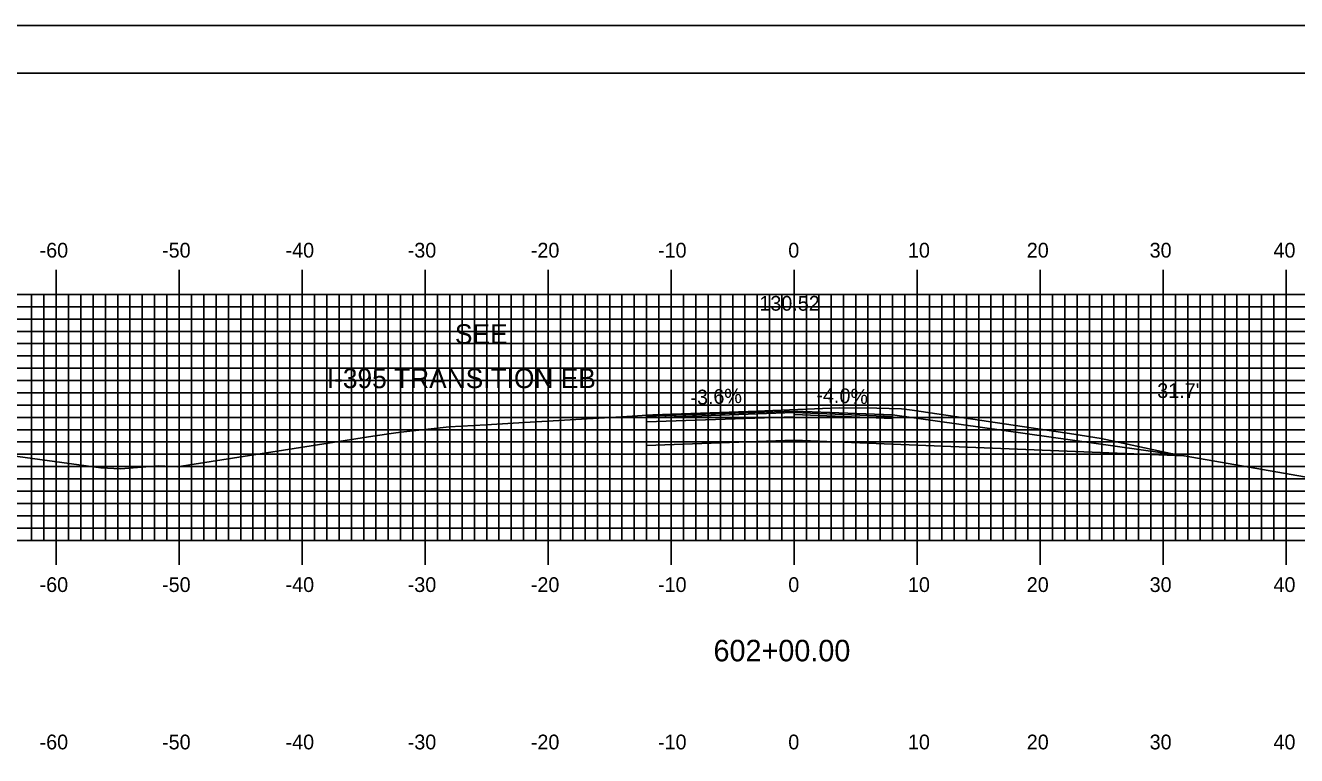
# Model space of a CAD drawing. Extents: x 841388 to 841731, y 363538 to 363758.
# Drawn here: x 841491.4 to 841594.7, y 363698.2 to 363757.6 of the extents above; entities that cross this region are included whole.
import ezdxf

# ---------------------------------------------------------------- set-up
doc = ezdxf.new("R2010")
doc.units = 0
for name, color, linetype in [('ANNOTATION', 7, 'Continuous'), ('BORDER', 7, 'Continuous'), ('D_Roadway_Centerline', 7, 'Continuous'), ('D_Roadway_Centerline_Text', 7, 'Continuous'), ('D_Roadway_Edge_Shoulder', 7, 'Continuous'), ('D_Roadway_Edge_TW', 7, 'Continuous'), ('D_Roadway_SubGrade', 7, 'Continuous'), ('D_Text_Standard', 7, 'Continuous'), ('H_V ANNOTATION', 7, 'Continuous'), ('M_Roadway_Centerline', 7, 'Continuous'), ('MAJOR', 7, 'Continuous'), ('MINOR', 7, 'Continuous'), ('PLOT BOUNDARY', 7, 'Continuous'), ('S_Roadway_Centerline', 7, 'Continuous')]:
    doc.layers.add(name, color=color, linetype=linetype)

msp = doc.modelspace()

# ---------------------------------------------------------------- linework, layer by layer
at = {"layer": 'ANNOTATION'}
for p, q in [((841541.86, 363725.68), (841541.86, 363723.43)), ((841553.86, 363726.12), (841553.86, 363723.87)), ((841561.86, 363725.8), (841561.86, 363723.55))]:
    msp.add_line(p, q, dxfattribs=at)
at = {"layer": 'BORDER'}
msp.add_lwpolyline([(841404.26, 363543.72), (841724.26, 363543.72), (841724.26, 363753.72), (841404.26, 363753.72)], close=True, dxfattribs=at)
at = {"layer": 'D_Roadway_Centerline'}
msp.add_lwpolyline([(841541.86, 363725.81), (841553.86, 363726.24), (841561.86, 363725.92)], dxfattribs=at)
at = {"layer": 'D_Roadway_Edge_Shoulder'}
msp.add_lwpolyline([(841553.86, 363726.24), (841561.86, 363725.92), (841561.86, 363725.8), (841553.86, 363726.12)], close=True, dxfattribs=at)
at = {"layer": 'D_Roadway_Edge_TW'}
msp.add_lwpolyline([(841541.86, 363725.81), (841553.86, 363726.24), (841553.86, 363726.12), (841541.86, 363725.68)], close=True, dxfattribs=at)
msp.add_lwpolyline([(841541.86, 363725.81), (841541.86, 363725.68)], dxfattribs=at)
at = {"layer": 'D_Roadway_SubGrade'}
for p, q in [((841541.86, 363734.28), (841541.86, 363725.68)), ((841541.86, 363725.68), (841541.86, 363723.43)), ((841553.86, 363726.12), (841553.86, 363723.87)), ((841561.86, 363725.8), (841561.86, 363723.55))]:
    msp.add_line(p, q, dxfattribs=at)
for points in [[(841553.86, 363726.12), (841553.86, 363725.78), (841541.86, 363725.35)], [(841541.86, 363725.68), (841541.86, 363723.43), (841553.86, 363723.87), (841561.86, 363723.55)], [(841553.86, 363726.12), (841553.86, 363725.95), (841561.86, 363725.63)], [(841561.86, 363723.55), (841585.53, 363722.6), (841561.86, 363725.92)]]:
    msp.add_lwpolyline(points, dxfattribs=at)
at = {"layer": 'MAJOR'}
for p, q in [((841493.86, 363737.73), (841493.86, 363735.72)), ((841503.86, 363737.73), (841503.86, 363735.72)), ((841513.86, 363737.73), (841513.86, 363735.72)), ((841523.86, 363737.73), (841523.86, 363735.72)), ((841533.86, 363737.73), (841533.86, 363735.72)), ((841543.86, 363737.73), (841543.86, 363735.72)), ((841553.86, 363737.73), (841553.86, 363735.72)), ((841563.86, 363737.73), (841563.86, 363735.72)), ((841573.86, 363737.73), (841573.86, 363735.72)), ((841583.86, 363737.73), (841583.86, 363735.72)), ((841593.86, 363737.73), (841593.86, 363735.72)), ((841413.86, 363735.72), (841693.86, 363735.72)), ((841413.86, 363735.72), (841693.86, 363735.72)), ((841493.86, 363715.72), (841493.86, 363735.72)), ((841503.86, 363715.72), (841503.86, 363735.72)), ((841513.86, 363715.72), (841513.86, 363735.72)), ((841523.86, 363715.72), (841523.86, 363735.72)), ((841533.86, 363715.72), (841533.86, 363735.72)), ((841543.86, 363715.72), (841543.86, 363735.72)), ((841553.86, 363715.72), (841553.86, 363735.72)), ((841563.86, 363715.72), (841563.86, 363735.72)), ((841573.86, 363715.72), (841573.86, 363735.72)), ((841583.86, 363715.72), (841583.86, 363735.72)), ((841593.86, 363715.72), (841593.86, 363735.72)), ((841413.86, 363730.72), (841693.86, 363730.72)), ((841413.86, 363725.72), (841693.86, 363725.72)), ((841413.86, 363720.72), (841693.86, 363720.72)), ((841413.86, 363715.72), (841693.86, 363715.72)), ((841413.86, 363715.72), (841693.86, 363715.72)), ((841493.86, 363713.72), (841493.86, 363715.72)), ((841503.86, 363713.72), (841503.86, 363715.72)), ((841513.86, 363713.72), (841513.86, 363715.72)), ((841523.86, 363713.72), (841523.86, 363715.72)), ((841533.86, 363713.72), (841533.86, 363715.72)), ((841543.86, 363713.72), (841543.86, 363715.72)), ((841553.86, 363713.72), (841553.86, 363715.72)), ((841563.86, 363713.72), (841563.86, 363715.72)), ((841573.86, 363713.72), (841573.86, 363715.72)), ((841583.86, 363713.72), (841583.86, 363715.72)), ((841593.86, 363713.72), (841593.86, 363715.72))]:
    msp.add_line(p, q, dxfattribs=at)
at = {"layer": 'MINOR'}
for p, q in [((841491.86, 363715.72), (841491.86, 363735.72)), ((841492.86, 363715.72), (841492.86, 363735.72)), ((841494.86, 363715.72), (841494.86, 363735.72)), ((841495.86, 363715.72), (841495.86, 363735.72)), ((841496.86, 363715.72), (841496.86, 363735.72)), ((841497.86, 363715.72), (841497.86, 363735.72)), ((841498.86, 363715.72), (841498.86, 363735.72)), ((841499.86, 363715.72), (841499.86, 363735.72)), ((841500.86, 363715.72), (841500.86, 363735.72)), ((841501.86, 363715.72), (841501.86, 363735.72)), ((841502.86, 363715.72), (841502.86, 363735.72)), ((841504.86, 363715.72), (841504.86, 363735.72)), ((841505.86, 363715.72), (841505.86, 363735.72)), ((841506.86, 363715.72), (841506.86, 363735.72)), ((841507.86, 363715.72), (841507.86, 363735.72)), ((841508.86, 363715.72), (841508.86, 363735.72)), ((841509.86, 363715.72), (841509.86, 363735.72)), ((841510.86, 363715.72), (841510.86, 363735.72)), ((841511.86, 363715.72), (841511.86, 363735.72)), ((841512.86, 363715.72), (841512.86, 363735.72)), ((841514.86, 363715.72), (841514.86, 363735.72)), ((841515.86, 363715.72), (841515.86, 363735.72)), ((841516.86, 363715.72), (841516.86, 363735.72)), ((841517.86, 363715.72), (841517.86, 363735.72)), ((841518.86, 363715.72), (841518.86, 363735.72)), ((841519.86, 363715.72), (841519.86, 363735.72)), ((841520.86, 363715.72), (841520.86, 363735.72)), ((841521.86, 363715.72), (841521.86, 363735.72)), ((841522.86, 363715.72), (841522.86, 363735.72)), ((841524.86, 363715.72), (841524.86, 363735.72)), ((841525.86, 363715.72), (841525.86, 363735.72)), ((841526.86, 363715.72), (841526.86, 363735.72)), ((841527.86, 363715.72), (841527.86, 363735.72)), ((841528.86, 363715.72), (841528.86, 363735.72)), ((841529.86, 363715.72), (841529.86, 363735.72)), ((841530.86, 363715.72), (841530.86, 363735.72)), ((841531.86, 363715.72), (841531.86, 363735.72)), ((841532.86, 363715.72), (841532.86, 363735.72)), ((841534.86, 363715.72), (841534.86, 363735.72)), ((841535.86, 363715.72), (841535.86, 363735.72)), ((841536.86, 363715.72), (841536.86, 363735.72)), ((841537.86, 363715.72), (841537.86, 363735.72)), ((841538.86, 363715.72), (841538.86, 363735.72)), ((841539.86, 363715.72), (841539.86, 363735.72)), ((841540.86, 363715.72), (841540.86, 363735.72)), ((841541.86, 363715.72), (841541.86, 363735.72)), ((841542.86, 363715.72), (841542.86, 363735.72)), ((841544.86, 363715.72), (841544.86, 363735.72)), ((841545.86, 363715.72), (841545.86, 363735.72)), ((841546.86, 363715.72), (841546.86, 363735.72)), ((841547.86, 363715.72), (841547.86, 363735.72)), ((841548.86, 363715.72), (841548.86, 363735.72)), ((841549.86, 363715.72), (841549.86, 363735.72)), ((841550.86, 363715.72), (841550.86, 363735.72)), ((841551.86, 363715.72), (841551.86, 363735.72)), ((841552.86, 363715.72), (841552.86, 363735.72)), ((841554.86, 363715.72), (841554.86, 363735.72)), ((841555.86, 363715.72), (841555.86, 363735.72)), ((841556.86, 363715.72), (841556.86, 363735.72)), ((841557.86, 363715.72), (841557.86, 363735.72)), ((841558.86, 363715.72), (841558.86, 363735.72)), ((841559.86, 363715.72), (841559.86, 363735.72)), ((841560.86, 363715.72), (841560.86, 363735.72)), ((841561.86, 363715.72), (841561.86, 363735.72)), ((841562.86, 363715.72), (841562.86, 363735.72)), ((841564.86, 363715.72), (841564.86, 363735.72)), ((841565.86, 363715.72), (841565.86, 363735.72)), ((841566.86, 363715.72), (841566.86, 363735.72)), ((841567.86, 363715.72), (841567.86, 363735.72)), ((841568.86, 363715.72), (841568.86, 363735.72)), ((841569.86, 363715.72), (841569.86, 363735.72)), ((841570.86, 363715.72), (841570.86, 363735.72)), ((841571.86, 363715.72), (841571.86, 363735.72)), ((841572.86, 363715.72), (841572.86, 363735.72)), ((841574.86, 363715.72), (841574.86, 363735.72)), ((841575.86, 363715.72), (841575.86, 363735.72)), ((841576.86, 363715.72), (841576.86, 363735.72)), ((841577.86, 363715.72), (841577.86, 363735.72)), ((841578.86, 363715.72), (841578.86, 363735.72)), ((841579.86, 363715.72), (841579.86, 363735.72)), ((841580.86, 363715.72), (841580.86, 363735.72)), ((841581.86, 363715.72), (841581.86, 363735.72)), ((841582.86, 363715.72), (841582.86, 363735.72)), ((841584.86, 363715.72), (841584.86, 363735.72)), ((841585.86, 363715.72), (841585.86, 363735.72)), ((841586.86, 363715.72), (841586.86, 363735.72)), ((841587.86, 363715.72), (841587.86, 363735.72)), ((841588.86, 363715.72), (841588.86, 363735.72)), ((841589.86, 363715.72), (841589.86, 363735.72)), ((841590.86, 363715.72), (841590.86, 363735.72)), ((841591.86, 363715.72), (841591.86, 363735.72)), ((841592.86, 363715.72), (841592.86, 363735.72)), ((841413.86, 363734.72), (841693.86, 363734.72)), ((841413.86, 363733.72), (841693.86, 363733.72)), ((841413.86, 363732.72), (841693.86, 363732.72)), ((841413.86, 363731.72), (841693.86, 363731.72)), ((841413.86, 363729.72), (841693.86, 363729.72)), ((841413.86, 363728.72), (841693.86, 363728.72)), ((841413.86, 363727.72), (841693.86, 363727.72)), ((841413.86, 363726.72), (841693.86, 363726.72)), ((841413.86, 363724.72), (841693.86, 363724.72)), ((841413.86, 363723.72), (841693.86, 363723.72)), ((841413.86, 363722.72), (841693.86, 363722.72)), ((841413.86, 363721.72), (841693.86, 363721.72)), ((841413.86, 363719.72), (841693.86, 363719.72)), ((841413.86, 363718.72), (841693.86, 363718.72)), ((841413.86, 363717.72), (841693.86, 363717.72)), ((841413.86, 363716.72), (841693.86, 363716.72))]:
    msp.add_line(p, q, dxfattribs=at)
at = {"layer": 'PLOT BOUNDARY'}
msp.add_lwpolyline([(841388.07, 363537.6), (841728.07, 363537.6), (841728.07, 363757.6), (841388.07, 363757.6)], close=True, dxfattribs=at)
at = {"layer": 'S_Roadway_Centerline'}
msp.add_lwpolyline([(841488.13, 363722.89), (841497.5, 363721.63), (841499.1, 363721.53), (841502.19, 363721.77), (841503.69, 363721.69), (841519.61, 363724.19), (841521.28, 363724.45), (841521.89, 363724.53), (841525.82, 363724.94), (841528.81, 363725.11), (841531, 363725.25), (841539.35, 363725.75), (841541.13, 363725.86), (841541.88, 363725.91), (841542.38, 363725.92), (841550.13, 363726.21), (841557.51, 363726.51), (841560.58, 363726.48), (841562.59, 363726.41), (841563.44, 363726.3), (841573.12, 363724.87), (841576.59, 363724.37), (841578.82, 363724), (841584.47, 363722.78), (841595.98, 363720.78)], dxfattribs=at)

# ---------------------------------------------------------------- texts
at = {"layer": 'ANNOTATION'}
for s, p in [('SEE', (841526.28, 363731.7)), ('I-395 TRANSITION EB', (841515.86, 363728.1))]:
    msp.add_text(s, height=1.6, dxfattribs=at).set_placement(p)
for s, rotation, p in [('-3.6%', 2.0618, (841545.44, 363726.74)), ('-4.0%', 357.7094, (841555.65, 363726.97))]:
    msp.add_text(s, height=1.2, rotation=rotation, dxfattribs=at).set_placement(p)
at = {"layer": 'D_Roadway_Centerline_Text'}
msp.add_text('130.52', height=1.2, dxfattribs=at).set_placement((841551.03, 363734.4))
at = {"layer": 'D_Text_Standard'}
msp.add_text("31.7'", height=1.2, dxfattribs=at).set_placement((841583.38, 363727.3))
at = {"layer": 'H_V ANNOTATION'}
for s, height, p in [('-60', 1.2, (841492.51, 363738.72)), ('-50', 1.2, (841502.47, 363738.72)), ('-40', 1.2, (841512.51, 363738.72)), ('-30', 1.2, (841522.44, 363738.72)), ('-20', 1.2, (841532.45, 363738.72)), ('-10', 1.2, (841542.79, 363738.72)), ('0', 1.2, (841553.38, 363738.72)), ('10', 1.2, (841563.11, 363738.72)), ('20', 1.2, (841572.77, 363738.72)), ('30', 1.2, (841582.76, 363738.72)), ('40', 1.2, (841592.83, 363738.72)), ('-60', 1.2, (841492.51, 363711.52)), ('-50', 1.2, (841502.47, 363711.52)), ('-40', 1.2, (841512.51, 363711.52)), ('-30', 1.2, (841522.44, 363711.52)), ('-20', 1.2, (841532.45, 363711.52)), ('-10', 1.2, (841542.79, 363711.52)), ('0', 1.2, (841553.38, 363711.52)), ('10', 1.2, (841563.11, 363711.52)), ('20', 1.2, (841572.77, 363711.52)), ('30', 1.2, (841582.76, 363711.52)), ('40', 1.2, (841592.83, 363711.52)), ('602+00.00', 1.75, (841547.3, 363705.88)), ('-60', 1.2, (841492.51, 363698.72)), ('-50', 1.2, (841502.47, 363698.72)), ('-40', 1.2, (841512.51, 363698.72)), ('-30', 1.2, (841522.44, 363698.72)), ('-20', 1.2, (841532.45, 363698.72)), ('-10', 1.2, (841542.79, 363698.72)), ('0', 1.2, (841553.38, 363698.72)), ('10', 1.2, (841563.11, 363698.72)), ('20', 1.2, (841572.77, 363698.72)), ('30', 1.2, (841582.76, 363698.72)), ('40', 1.2, (841592.83, 363698.72))]:
    msp.add_text(s, height=height, dxfattribs=at).set_placement(p)
at = {"layer": 'M_Roadway_Centerline'}
for s, p in [('C', (841541.87, 363725.91)), ('L', (841541.88, 363725.91))]:
    msp.add_text(s, height=0.0146, dxfattribs=at).set_placement(p)

doc.saveas('drawing.dxf')
